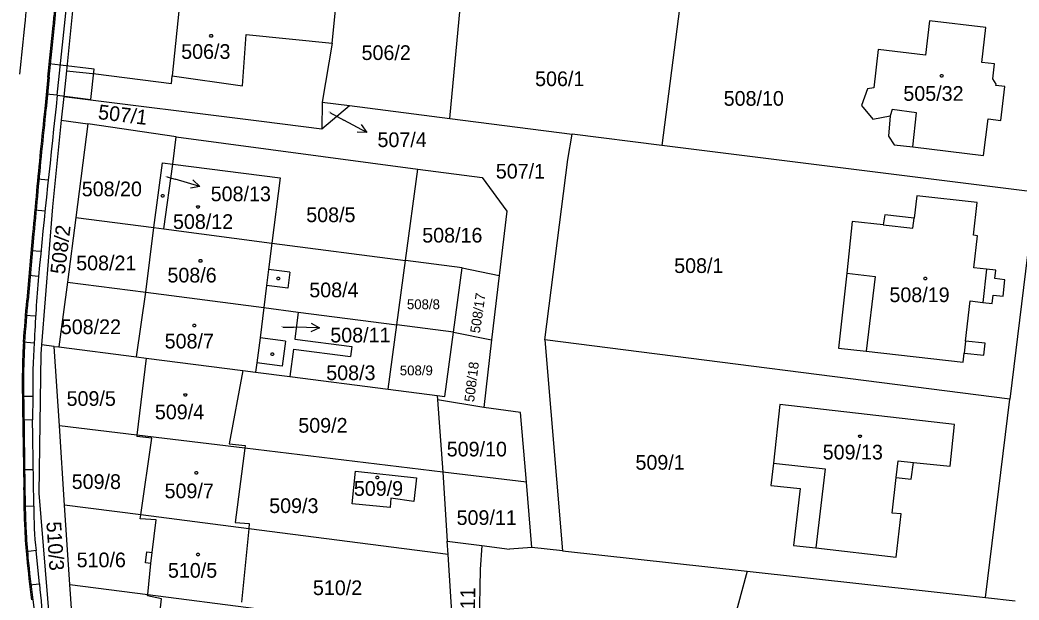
# Model space of a CAD drawing. Extents: x -639590 to -639298, y -1193269 to -1192863.
# Drawn here: x -639511.2 to -639395.8, y -1192983.6 to -1192916.5 of the extents above; entities that cross this region are included whole.
import ezdxf

# ---------------------------------------------------------------- set-up
doc = ezdxf.new("R2010")
doc.units = 0
for name, color, linetype in [('Vrstva 1', 7, 'Continuous'), ('Vrstva 19', 7, 'Continuous'), ('Vrstva 2', 7, 'Continuous'), ('Vrstva 20', 7, 'Continuous'), ('Vrstva 22', 7, 'Continuous'), ('Vrstva 4', 7, 'Continuous'), ('Vrstva 5', 7, 'Continuous'), ('Vrstva 7', 7, 'Continuous')]:
    doc.layers.add(name, color=color, linetype=linetype)

msp = doc.modelspace()

# ---------------------------------------------------------------- linework, layer by layer
at = {"layer": 'Vrstva 1'}
for p, q in [((-639504.16, -1192906.23), (-639505.82, -1192922.39)), ((-639461.52, -1192927.91), (-639460.05, -1192911.94)), ((-639492.68, -1192913.98), (-639493.6, -1192922.99)), ((-639475.12, -1192919.21), (-639474.65, -1192914.63)), ((-639434.99, -1192915.19), (-639437.01, -1192931.02)), ((-639406.1, -1192916.63), (-639406.58, -1192920.61)), ((-639399.58, -1192917.41), (-639406.1, -1192916.63)), ((-639400.06, -1192921.43), (-639399.58, -1192917.41)), ((-639475.12, -1192919.21), (-639476.29, -1192926.03)), ((-639412.03, -1192919.95), (-639412.54, -1192924.38)), ((-639406.58, -1192920.61), (-639412.03, -1192919.95)), ((-639398.59, -1192921.61), (-639400.06, -1192921.43)), ((-639398.8, -1192923.34), (-639398.59, -1192921.61)), ((-639505.82, -1192922.39), (-639506.13, -1192925.38)), ((-639505.82, -1192922.39), (-639502.41, -1192922.75)), ((-639502.41, -1192922.75), (-639493.69, -1192923.85)), ((-639493.69, -1192923.85), (-639493.6, -1192922.99)), ((-639398.41, -1192923.95), (-639398.8, -1192923.34)), ((-639398.43, -1192924.1), (-639398.41, -1192923.95)), ((-639397.39, -1192924.22), (-639398.43, -1192924.1)), ((-639397.86, -1192928.14), (-639397.39, -1192924.22)), ((-639506.13, -1192925.38), (-639506.41, -1192928.09)), ((-639506.13, -1192925.38), (-639483.29, -1192928.23)), ((-639413.28, -1192924.5), (-639413.96, -1192926.43)), ((-639412.54, -1192924.38), (-639413.28, -1192924.5)), ((-639476.29, -1192926.03), (-639476.3, -1192929.1)), ((-639476.3, -1192929.1), (-639473.13, -1192926.43)), ((-639476.29, -1192926.03), (-639473.13, -1192926.43)), ((-639473.13, -1192926.43), (-639461.52, -1192927.91)), ((-639413.96, -1192926.43), (-639412.64, -1192928)), ((-639412.64, -1192928), (-639410.64, -1192927.59)), ((-639410.64, -1192927.59), (-639410.84, -1192929.94)), ((-639506.41, -1192928.09), (-639507.43, -1192938.15)), ((-639506.41, -1192928.09), (-639503.33, -1192928.54)), ((-639503.33, -1192928.54), (-639504.74, -1192939.37)), ((-639493.13, -1192930.04), (-639503.33, -1192928.54)), ((-639483.29, -1192928.23), (-639476.3, -1192929.1)), ((-639461.52, -1192927.91), (-639447.4, -1192929.71)), ((-639399.85, -1192932.18), (-639399.34, -1192927.96)), ((-639399.34, -1192927.96), (-639397.86, -1192928.14)), ((-639447.88, -1192932.66), (-639447.4, -1192929.71)), ((-639437.01, -1192931.02), (-639447.4, -1192929.71)), ((-639410.84, -1192929.94), (-639410.19, -1192930.95)), ((-639493.54, -1192933.18), (-639493.13, -1192930.04)), ((-639493.13, -1192930.04), (-639465.22, -1192933.76)), ((-639393.89, -1192936.45), (-639437.01, -1192931.02)), ((-639410.19, -1192930.95), (-639408.01, -1192931.21)), ((-639408.01, -1192931.21), (-639399.85, -1192932.18)), ((-639495.71, -1192940.54), (-639494.72, -1192933.03)), ((-639494.72, -1192933.03), (-639493.54, -1192933.18)), ((-639494.57, -1192940.69), (-639493.54, -1192933.18)), ((-639493.54, -1192933.18), (-639481.11, -1192934.79)), ((-639450.53, -1192953.5), (-639447.88, -1192932.66)), ((-639466.65, -1192944.34), (-639465.22, -1192933.76)), ((-639465.22, -1192933.76), (-639457.78, -1192934.75)), ((-639481.11, -1192934.79), (-639482.07, -1192942.33)), ((-639457.78, -1192934.75), (-639454.93, -1192938.64)), ((-639407.58, -1192936.84), (-639407.89, -1192939.43)), ((-639400.58, -1192937.64), (-639407.58, -1192936.84)), ((-639393.89, -1192936.45), (-639396.82, -1192960.36)), ((-639401.01, -1192941.42), (-639400.58, -1192937.64)), ((-639507.43, -1192938.15), (-639508.7, -1192954.08)), ((-639454.93, -1192938.64), (-639455.81, -1192946.09)), ((-639411.26, -1192939.05), (-639411.45, -1192940.22)), ((-639407.89, -1192939.43), (-639411.26, -1192939.05)), ((-639504.74, -1192939.37), (-639505.71, -1192946.84)), ((-639504.74, -1192939.37), (-639495.71, -1192940.54)), ((-639415.02, -1192939.83), (-639415.66, -1192945.81)), ((-639411.45, -1192940.22), (-639415.02, -1192939.83)), ((-639496.66, -1192948), (-639495.71, -1192940.54)), ((-639495.71, -1192940.54), (-639494.57, -1192940.69)), ((-639494.57, -1192940.69), (-639482.07, -1192942.33)), ((-639400.57, -1192941.47), (-639401.01, -1192941.42)), ((-639400.99, -1192945.17), (-639400.57, -1192941.47)), ((-639482.07, -1192942.33), (-639482.46, -1192945.37)), ((-639482.07, -1192942.33), (-639466.65, -1192944.34)), ((-639467.65, -1192951.78), (-639466.65, -1192944.34)), ((-639460.11, -1192945.19), (-639466.65, -1192944.34)), ((-639480, -1192945.68), (-639482.46, -1192945.37)), ((-639480, -1192945.68), (-639480.24, -1192947.55)), ((-639461.1, -1192952.63), (-639460.11, -1192945.19)), ((-639460.11, -1192945.19), (-639455.81, -1192946.09)), ((-639455.81, -1192946.09), (-639456.69, -1192953.53)), ((-639415.66, -1192945.81), (-639416.62, -1192954.46)), ((-639399.5, -1192945.34), (-639400.99, -1192945.17)), ((-639398.43, -1192945.46), (-639399.5, -1192945.34)), ((-639398.54, -1192946.42), (-639398.43, -1192945.46)), ((-639505.71, -1192946.84), (-639506.68, -1192954.34)), ((-639505.71, -1192946.84), (-639496.66, -1192948)), ((-639482.69, -1192947.23), (-639483.01, -1192949.78)), ((-639480.24, -1192947.55), (-639482.69, -1192947.23)), ((-639397.38, -1192946.56), (-639398.54, -1192946.42)), ((-639397.6, -1192948.47), (-639397.38, -1192946.56)), ((-639497.71, -1192955.46), (-639496.66, -1192948)), ((-639496.66, -1192948), (-639483.01, -1192949.78)), ((-639398.87, -1192949.31), (-639398.76, -1192948.34)), ((-639398.76, -1192948.34), (-639397.6, -1192948.47)), ((-639401.94, -1192953.65), (-639401.41, -1192949.02)), ((-639401.41, -1192949.02), (-639399.93, -1192949.19)), ((-639399.93, -1192949.19), (-639398.87, -1192949.31)), ((-639483.01, -1192949.78), (-639483.45, -1192953.28)), ((-639483.01, -1192949.78), (-639479.04, -1192950.3)), ((-639479.04, -1192950.3), (-639479.44, -1192953.44)), ((-639479.04, -1192950.3), (-639467.65, -1192951.78)), ((-639468.65, -1192959.23), (-639467.65, -1192951.78)), ((-639461.1, -1192952.63), (-639467.65, -1192951.78)), ((-639462.1, -1192960.08), (-639461.1, -1192952.63)), ((-639461.1, -1192952.63), (-639456.69, -1192953.53)), ((-639508.7, -1192954.08), (-639508.78, -1192955.14)), ((-639507.25, -1192954.27), (-639508.7, -1192954.08)), ((-639506.64, -1192963.45), (-639507.25, -1192954.27)), ((-639507.25, -1192954.27), (-639506.68, -1192954.34)), ((-639480.51, -1192953.66), (-639483.45, -1192953.28)), ((-639480.51, -1192953.66), (-639480.88, -1192956.55)), ((-639479.44, -1192953.44), (-639472.84, -1192954.29)), ((-639456.69, -1192953.53), (-639457.61, -1192961.33)), ((-639396.82, -1192960.36), (-639450.53, -1192953.5)), ((-639450.53, -1192953.5), (-639448.49, -1192977.92)), ((-639399.65, -1192953.91), (-639401.94, -1192953.65)), ((-639399.81, -1192955.3), (-639399.65, -1192953.91)), ((-639508.78, -1192955.14), (-639509.02, -1192971.25)), ((-639506.68, -1192954.34), (-639497.71, -1192955.46)), ((-639479.59, -1192954.6), (-639479.99, -1192957.77)), ((-639479.59, -1192954.6), (-639472.99, -1192955.45)), ((-639472.84, -1192954.29), (-639472.99, -1192955.45)), ((-639416.62, -1192954.46), (-639413.41, -1192954.82)), ((-639413.41, -1192954.82), (-639402.21, -1192956.09)), ((-639402.21, -1192956.09), (-639402.09, -1192955.04)), ((-639402.09, -1192955.04), (-639399.81, -1192955.3)), ((-639497.71, -1192955.46), (-639496.62, -1192955.64)), ((-639496.62, -1192955.64), (-639497.68, -1192964.53)), ((-639496.62, -1192955.64), (-639485.45, -1192957.07)), ((-639483.82, -1192956.18), (-639483.96, -1192957.26)), ((-639480.88, -1192956.55), (-639483.82, -1192956.18)), ((-639485.45, -1192957.07), (-639487.03, -1192965.52)), ((-639485.45, -1192957.07), (-639483.96, -1192957.26)), ((-639483.96, -1192957.26), (-639479.99, -1192957.77)), ((-639479.99, -1192957.77), (-639468.65, -1192959.23)), ((-639468.65, -1192959.23), (-639463, -1192959.96)), ((-639463, -1192959.96), (-639462.96, -1192960.46)), ((-639463, -1192959.96), (-639462.1, -1192960.08)), ((-639462.96, -1192960.46), (-639462.33, -1192968.8)), ((-639457.61, -1192961.33), (-639462.96, -1192960.46)), ((-639423.39, -1192961), (-639424.14, -1192967.77)), ((-639403.2, -1192963.32), (-639423.39, -1192961)), ((-639399.63, -1192983.32), (-639396.82, -1192960.36)), ((-639453.34, -1192961.9), (-639457.61, -1192961.33)), ((-639452.66, -1192969.99), (-639453.34, -1192961.9)), ((-639506.04, -1192972.62), (-639506.64, -1192963.45)), ((-639497.68, -1192964.53), (-639506.64, -1192963.45)), ((-639403.7, -1192968.14), (-639403.2, -1192963.32)), ((-639497.68, -1192964.53), (-639497.7, -1192964.68)), ((-639485.22, -1192966.04), (-639497.68, -1192964.53)), ((-639495.97, -1192964.89), (-639497.7, -1192964.68)), ((-639497.23, -1192973.76), (-639495.97, -1192964.89)), ((-639487.03, -1192965.52), (-639485.18, -1192965.75)), ((-639485.18, -1192965.75), (-639485.22, -1192966.04)), ((-639485.22, -1192966.04), (-639486.31, -1192974.64)), ((-639462.33, -1192968.8), (-639485.22, -1192966.04)), ((-639424.14, -1192967.77), (-639424.43, -1192970.35)), ((-639408.21, -1192969.62), (-639407.96, -1192967.68)), ((-639407.96, -1192967.68), (-639403.7, -1192968.14)), ((-639472.79, -1192972.46), (-639472.41, -1192968.71)), ((-639472.41, -1192968.71), (-639465.38, -1192969.47)), ((-639452.66, -1192969.99), (-639462.33, -1192968.8)), ((-639462.33, -1192968.8), (-639461.83, -1192976.78)), ((-639465.38, -1192969.47), (-639465.67, -1192972.19)), ((-639452.04, -1192977.53), (-639452.66, -1192969.99)), ((-639424.43, -1192970.35), (-639421.05, -1192970.72)), ((-639410.42, -1192973.55), (-639409.95, -1192969.42)), ((-639409.95, -1192969.42), (-639408.21, -1192969.62)), ((-639509.02, -1192971.25), (-639507.5, -1192989.45)), ((-639421.05, -1192970.72), (-639421.81, -1192977.28)), ((-639505.43, -1192981.79), (-639506.04, -1192972.62)), ((-639497.23, -1192973.76), (-639506.04, -1192972.62)), ((-639468.43, -1192972.89), (-639472.79, -1192972.46)), ((-639468.33, -1192971.82), (-639468.43, -1192972.89)), ((-639465.67, -1192972.19), (-639468.33, -1192971.82)), ((-639497.3, -1192974.23), (-639497.23, -1192973.76)), ((-639484.75, -1192975.37), (-639497.23, -1192973.76)), ((-639409.39, -1192973.64), (-639410.42, -1192973.55)), ((-639409.96, -1192978.65), (-639409.39, -1192973.64)), ((-639495.44, -1192974.33), (-639497.3, -1192974.23)), ((-639495.9, -1192978.09), (-639495.44, -1192974.33)), ((-639486.31, -1192974.64), (-639484.69, -1192974.77)), ((-639484.69, -1192974.77), (-639484.75, -1192975.37)), ((-639484.75, -1192975.37), (-639485.61, -1192983.86)), ((-639461.73, -1192978.35), (-639484.75, -1192975.37)), ((-639461.83, -1192976.78), (-639457.81, -1192977.3)), ((-639461.73, -1192978.35), (-639461.83, -1192976.78)), ((-639457.81, -1192977.3), (-639458.02, -1192980.06)), ((-639457.81, -1192977.3), (-639454.62, -1192977.71)), ((-639421.81, -1192977.28), (-639419.23, -1192977.58)), ((-639496.7, -1192979.3), (-639496.54, -1192978.02)), ((-639496.54, -1192978.02), (-639495.9, -1192978.09)), ((-639461.13, -1192987.55), (-639461.73, -1192978.35)), ((-639452.04, -1192977.53), (-639454.62, -1192977.71)), ((-639448.49, -1192977.92), (-639452.04, -1192977.53)), ((-639448.49, -1192977.92), (-639427.17, -1192980.28)), ((-639419.23, -1192977.58), (-639409.96, -1192978.65)), ((-639496.06, -1192979.38), (-639496.7, -1192979.3)), ((-639496.42, -1192982.96), (-639496.06, -1192979.38)), ((-639458.02, -1192980.06), (-639458.26, -1192995.21)), ((-639427.17, -1192980.28), (-639429.8, -1192989.92)), ((-639427.17, -1192980.28), (-639399.63, -1192983.32)), ((-639504.82, -1192990.96), (-639505.43, -1192981.79)), ((-639505.43, -1192981.79), (-639496.42, -1192982.96)), ((-639496.42, -1192982.96), (-639483.9, -1192984.59)), ((-639399.63, -1192983.32), (-639396.19, -1192983.7))]:
    msp.add_line(p, q, dxfattribs=at)
at = {"layer": 'Vrstva 19'}
for p, q in [((-639507.95, -1192923.13), (-639508.33, -1192926.78)), ((-639509.73, -1192941.27), (-639510.41, -1192948.9)), ((-639510.89, -1192961.31), (-639510.76, -1192970.58))]:
    msp.add_line(p, q, dxfattribs=at)
for centre, radius, start, end in [((-640505.63, -1192817.43), 1000, 354.29543, 354.39908), ((-640505.63, -1192817.43), 1003.25, 354.29543, 354.39908), ((-641546.01, -1192712.41), 2045.67, 354.09679, 354.26487), ((-641546.01, -1192712.41), 2048.92, 354.09679, 354.26487), ((-638039.17, -1193078.86), 1477.01, 174.09044, 174.28397), ((-638765.76, -1193005.72), 746.75, 174.31453, 174.66566), ((-637998.74, -1193076.46), 1517.02, 174.69877, 174.88721), ((-639366.3, -1192962.73), 144.78, 174.5256, 176.4609), ((-639439.16, -1192957.83), 71.75, 176.7658, 178.8764), ((-639362.14, -1192958.46), 148.78, 179.2067, 181.0911), ((-639365.99, -1192969.45), 144.78, 180.4545, 182.3898), ((-639438.97, -1192972.1), 71.75, 182.6947, 185.3222), ((-639366.33, -1192964.54), 144.78, 185.6271, 187.5624)]:
    msp.add_arc(centre, radius, start, end, dxfattribs=at)
at = {"layer": 'Vrstva 20'}
for p, q in [((-639506.88, -1192925.23), (-639505.56, -1192912.55)), ((-639506.52, -1192921.73), (-639507.8, -1192921.6)), ((-639507.8, -1192923.15), (-639508.18, -1192926.8)), ((-639506.88, -1192925.23), (-639508.16, -1192925.1)), ((-639507.91, -1192935.06), (-639509.15, -1192934.95)), ((-639508.29, -1192938.63), (-639509.48, -1192938.52)), ((-639509.58, -1192941.28), (-639510.26, -1192948.92)), ((-639508.77, -1192943.3), (-639509.9, -1192943.2)), ((-639509.06, -1192946.19), (-639510.16, -1192946.09)), ((-639509.38, -1192950.79), (-639510.57, -1192950.69)), ((-639509.55, -1192953.88), (-639510.8, -1192953.8)), ((-639509.69, -1192960.05), (-639510.91, -1192960.06)), ((-639509.69, -1192960.05), (-639509.73, -1192962.77)), ((-639510.74, -1192961.31), (-639510.61, -1192970.58)), ((-639509.73, -1192962.77), (-639510.87, -1192962.79)), ((-639509.64, -1192968.55), (-639510.79, -1192968.56)), ((-639509.58, -1192972.76), (-639510.73, -1192972.78)), ((-639509.33, -1192977.89), (-639510.47, -1192978.03)), ((-639508.94, -1192981.75), (-639509.33, -1192977.89)), ((-639508.94, -1192981.75), (-639510.07, -1192981.88)), ((-639509.7, -1192983.59), (-639509.32, -1192986.56))]:
    msp.add_line(p, q, dxfattribs=at)
for centre, radius, start, end in [((-640505.63, -1192817.43), 1003.4, 354.29543, 354.39908), ((-641546.01, -1192712.41), 2049.07, 354.09679, 354.26487), ((-636441.8, -1193254.52), 3082.72, 173.86801, 174.25961), ((-638039.17, -1193078.86), 1476.86, 174.09044, 174.28397), ((-638765.76, -1193005.72), 746.6, 174.31453, 174.66566), ((-637998.74, -1193076.46), 1516.87, 174.69877, 174.88721), ((-639256.41, -1192966.11), 253.43, 175.4905, 177.229), ((-639366.3, -1192962.73), 144.63, 174.5256, 176.4609), ((-639439.16, -1192957.83), 71.6, 176.7658, 178.8764), ((-639438.45, -1192958.6), 71.26, 176.1992, 181.167), ((-639362.14, -1192958.46), 148.63, 179.2067, 181.0911), ((-695875.65, -1193814.37), 56372.35, 0.855428, 0.865581), ((-639365.99, -1192969.45), 144.63, 180.4545, 182.3898), ((-639472.74, -1192973.54), 36.84, 178.7815, 186.7755), ((-639438.97, -1192972.1), 71.6, 182.6947, 185.3222), ((-639366.33, -1192964.54), 144.63, 185.6271, 187.5624), ((-639417.6, -1192974.02), 91.67, 184.8348, 188.0943)]:
    msp.add_arc(centre, radius, start, end, dxfattribs=at)
at = {"layer": 'Vrstva 22'}
for p, q in [((-639502.63, -1192922.2), (-639506.52, -1192921.73)), ((-639503, -1192925.72), (-639502.63, -1192922.2)), ((-639506.88, -1192925.23), (-639503, -1192925.72))]:
    msp.add_line(p, q, dxfattribs=at)
at = {"layer": 'Vrstva 4'}
for p, q in [((-639485.46, -1192924.14), (-639485.05, -1192918.2)), ((-639485.05, -1192918.2), (-639475.12, -1192919.21)), ((-639493.6, -1192922.99), (-639485.46, -1192924.14)), ((-639410.42, -1192926.88), (-639410.64, -1192927.59)), ((-639407.59, -1192927.25), (-639410.42, -1192926.88)), ((-639408.01, -1192931.21), (-639407.59, -1192927.25)), ((-639411.45, -1192940.22), (-639408.04, -1192940.58)), ((-639408.04, -1192940.58), (-639407.89, -1192939.43)), ((-639482.46, -1192945.37), (-639482.69, -1192947.23)), ((-639415.66, -1192945.81), (-639412.39, -1192946.2)), ((-639399.5, -1192945.34), (-639399.93, -1192949.19)), ((-639412.39, -1192946.2), (-639413.41, -1192954.82)), ((-639483.45, -1192953.28), (-639483.82, -1192956.18)), ((-639401.94, -1192953.65), (-639402.09, -1192955.04)), ((-639424.14, -1192967.77), (-639418.17, -1192968.44)), ((-639409.95, -1192969.42), (-639409.72, -1192967.49)), ((-639409.72, -1192967.49), (-639407.96, -1192967.68)), ((-639418.17, -1192968.44), (-639419.23, -1192977.58)), ((-639496.06, -1192979.38), (-639495.9, -1192978.09)), ((-639496.44, -1192983.12), (-639496.42, -1192982.96)), ((-639494.82, -1192983.46), (-639496.44, -1192983.12)), ((-639495.22, -1192986.76), (-639494.82, -1192983.46))]:
    msp.add_line(p, q, dxfattribs=at)
at = {"layer": 'Vrstva 5'}
for points in [[(-639489.01, -1192918.22), (-639488.92, -1192918.37), (-639489.01, -1192918.52), (-639489.19, -1192918.52), (-639489.28, -1192918.37), (-639489.19, -1192918.22)], [(-639404.6, -1192922.82), (-639404.51, -1192922.97), (-639404.6, -1192923.12), (-639404.78, -1192923.12), (-639404.87, -1192922.97), (-639404.78, -1192922.82)], [(-639494.62, -1192936.7), (-639494.53, -1192936.85), (-639494.62, -1192937), (-639494.8, -1192937), (-639494.89, -1192936.85), (-639494.8, -1192936.7)], [(-639490.54, -1192938), (-639490.45, -1192938.15), (-639490.54, -1192938.3), (-639490.72, -1192938.3), (-639490.81, -1192938.15), (-639490.72, -1192938)], [(-639490.24, -1192944.24), (-639490.15, -1192944.39), (-639490.24, -1192944.54), (-639490.42, -1192944.54), (-639490.51, -1192944.39), (-639490.42, -1192944.24)], [(-639481.25, -1192946.27), (-639481.16, -1192946.42), (-639481.25, -1192946.57), (-639481.43, -1192946.57), (-639481.52, -1192946.42), (-639481.43, -1192946.27)], [(-639406.49, -1192946.28), (-639406.4, -1192946.43), (-639406.49, -1192946.58), (-639406.67, -1192946.58), (-639406.76, -1192946.43), (-639406.67, -1192946.28)], [(-639490.95, -1192951.7), (-639490.86, -1192951.85), (-639490.95, -1192952), (-639491.13, -1192952), (-639491.22, -1192951.85), (-639491.13, -1192951.7)], [(-639481.95, -1192955.01), (-639481.86, -1192955.16), (-639481.95, -1192955.31), (-639482.13, -1192955.31), (-639482.22, -1192955.16), (-639482.13, -1192955.01)], [(-639492, -1192959.74), (-639491.91, -1192959.89), (-639492, -1192960.04), (-639492.18, -1192960.04), (-639492.27, -1192959.89), (-639492.18, -1192959.74)], [(-639414.05, -1192964.52), (-639413.96, -1192964.67), (-639414.05, -1192964.82), (-639414.23, -1192964.82), (-639414.32, -1192964.67), (-639414.23, -1192964.52)], [(-639490.72, -1192968.75), (-639490.63, -1192968.9), (-639490.72, -1192969.05), (-639490.9, -1192969.05), (-639490.99, -1192968.9), (-639490.9, -1192968.75)], [(-639469.81, -1192969.29), (-639469.72, -1192969.44), (-639469.81, -1192969.59), (-639469.99, -1192969.59), (-639470.08, -1192969.44), (-639469.99, -1192969.29)], [(-639490.52, -1192978.18), (-639490.43, -1192978.33), (-639490.52, -1192978.48), (-639490.7, -1192978.48), (-639490.79, -1192978.33), (-639490.7, -1192978.18)]]:
    msp.add_lwpolyline(points, close=True, dxfattribs=at)
at = {"layer": 'Vrstva 7'}
for p, q in [((-639475.4, -1192927.22), (-639473.76, -1192928.1)), ((-639471.12, -1192929.52), (-639473.76, -1192928.1)), ((-639494.23, -1192934.66), (-639493.27, -1192934.94)), ((-639490.39, -1192935.78), (-639493.27, -1192934.94)), ((-639480.81, -1192952.04), (-639479.57, -1192952.06)), ((-639476.57, -1192952.11), (-639479.57, -1192952.06))]:
    msp.add_line(p, q, dxfattribs=at)
for points in [[(-639471.76, -1192928.61), (-639471.12, -1192929.52), (-639472.23, -1192929.49)], [(-639491.21, -1192935.02), (-639490.39, -1192935.78), (-639491.49, -1192935.98)], [(-639477.56, -1192951.59), (-639476.57, -1192952.11), (-639477.58, -1192952.59)]]:
    msp.add_lwpolyline(points, dxfattribs=at)

# ---------------------------------------------------------------- texts
at = {"layer": 'Vrstva 2'}
for s, height, p in [('506/3', 1.7, (-639492.56, -1192921.02)), ('506/2', 1.7, (-639471.72, -1192921.15)), ('506/1', 1.7, (-639451.67, -1192924.17)), ('505/32', 1.7, (-639409.12, -1192925.87)), ('508/10', 1.7, (-639429.88, -1192926.44)), ('507/4', 0.1, (-639475.6, -1192927.22)), ('507/1', 1.7, (-639456.21, -1192934.86)), ('508/13', 0.1, (-639494.46, -1192934.66)), ('508/20', 1.7, (-639504.05, -1192936.91)), ('508/5', 1.7, (-639478.11, -1192939.9)), ('508/12', 1.7, (-639493.51, -1192940.69)), ('508/16', 1.7, (-639464.71, -1192942.26)), ('508/21', 1.7, (-639504.69, -1192945.47)), ('508/1', 1.7, (-639435.6, -1192945.78)), ('508/6', 1.7, (-639494.15, -1192946.88)), ('508/4', 1.7, (-639477.76, -1192948.59)), ('508/19', 1.7, (-639410.73, -1192949.15)), ('508/8', 1.14, (-639466.48, -1192949.97)), ('508/22', 1.7, (-639506.47, -1192952.85)), ('508/11', 0.1, (-639481.02, -1192952.04)), ('508/7', 1.7, (-639494.47, -1192954.51)), ('508/3', 1.7, (-639475.8, -1192958.17)), ('508/9', 1.14, (-639467.3, -1192957.62)), ('509/5', 1.7, (-639505.8, -1192961.15)), ('509/4', 1.7, (-639495.6, -1192962.7)), ('509/2', 1.7, (-639479.03, -1192964.25)), ('509/10', 1.7, (-639461.88, -1192967)), ('509/13', 1.7, (-639418.44, -1192967.35)), ('509/1', 1.7, (-639440.07, -1192968.53)), ('509/8', 1.7, (-639505.21, -1192970.76)), ('509/7', 1.7, (-639494.48, -1192971.83)), ('509/9', 1.7, (-639472.61, -1192971.55)), ('509/3', 1.7, (-639482.39, -1192973.54)), ('509/11', 1.7, (-639460.74, -1192974.92)), ('510/6', 1.7, (-639504.64, -1192979.81)), ('510/5', 1.7, (-639494.09, -1192981.02)), ('510/2', 1.7, (-639477.34, -1192983.03))]:
    msp.add_text(s, height=height, dxfattribs=at).set_placement(p)
for s, height, rotation, p in [('507/1', 1.7, 352.9906, (-639502.23, -1192927.97)), ('508/2', 1.7, 83.0789, (-639506.01, -1192945.99)), ('508/17', 1.14, 81.6465, (-639458.06, -1192952.8)), ('508/18', 1.14, 83.0789, (-639458.72, -1192960.75)), ('510/3', 1.7, 273.7592, (-639508.14, -1192974.58)), ('510/11', 1.7, 89.5533, (-639458.64, -1192989.11))]:
    msp.add_text(s, height=height, rotation=rotation, dxfattribs=at).set_placement(p)
at = {"layer": 'Vrstva 7'}
for s, p in [('507/4', (-639469.88, -1192931.22)), ('508/13', (-639489.15, -1192937.48)), ('508/11', (-639475.33, -1192953.81))]:
    msp.add_text(s, height=1.7, dxfattribs=at).set_placement(p)

doc.saveas('drawing.dxf')
